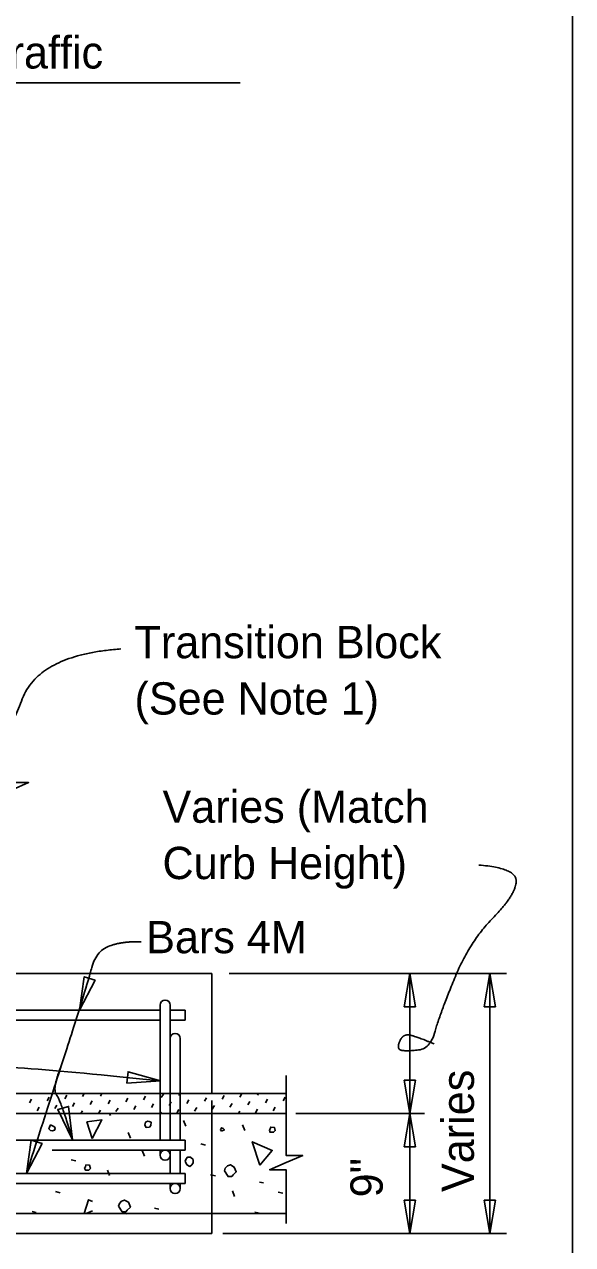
# Model space of a CAD drawing. Extents: x 0 to 41.1, y 0 to 25.9.
# Drawn here: x 37.62 to 41.05, y 6.17 to 13.8 of the extents above; entities that cross this region are included whole.
import ezdxf

# ---------------------------------------------------------------- set-up
doc = ezdxf.new("R2010")
doc.units = 0
for name, color, linetype in [('Dimension', 7, 'Continuous'), ('ExistSuperStruct', 7, 'Continuous'), ('Miscellaneous', 7, 'Continuous'), ('Miscellaneous1', 7, 'Continuous'), ('Rebar', 7, 'Continuous'), ('SubStrConc', 7, 'Continuous'), ('SubStrConc_h', 7, 'Continuous'), ('TextStructures', 7, 'Continuous')]:
    doc.layers.add(name, color=color, linetype=linetype)

msp = doc.modelspace()

# ---------------------------------------------------------------- linework, layer by layer
at = {"layer": 'Dimension'}
for p, q in [((38.8471, 13.433), (35.0367, 13.433)), ((35.76, 13.433), (38.9734, 13.433)), ((38.9734, 13.433), (38.8471, 13.433)), ((38.9044, 7.8689), (40.6367, 7.8689)), ((40.033, 7.8689), (40.033, 6.2439)), ((40.533, 7.8689), (40.533, 6.2439)), ((39.32, 6.9939), (40.1255, 6.9939)), ((38.8645, 6.2439), (40.6367, 6.2439))]:
    msp.add_line(p, q, dxfattribs=at)
for points in [[(0, 0), (41.0506, 0), (41.0506, 25.9461), (0, 25.9461)], [(40.033, 7.8689), (39.9978, 7.6607), (40.0683, 7.6607)], [(40.533, 7.8689), (40.4978, 7.6607), (40.5683, 7.6607)], [(37.9674, 7.6398), (38.0655, 7.8268), (37.9984, 7.8487)], [(38.4751, 7.1983), (38.2715, 7.2544), (38.2644, 7.1842)], [(40.033, 6.9939), (39.9978, 7.2022), (40.0683, 7.2022)], [(37.9247, 6.8286), (37.8998, 7.0383), (37.8321, 7.0184)], [(40.033, 6.9939), (39.9978, 6.7857), (40.0683, 6.7857)], [(37.6361, 6.6189), (37.7342, 6.806), (37.6671, 6.8278)], [(40.033, 6.2439), (40.0683, 6.4522), (39.9978, 6.4522)], [(40.533, 6.2439), (40.5683, 6.4522), (40.4978, 6.4522)]]:
    msp.add_lwpolyline(points, close=True, dxfattribs=at)
for points in [[(37.5468, 8.0879), (37.5468, 8.9711), (37.4435, 8.9711), (37.5468, 9.0161), (37.6502, 9.0611), (37.5468, 9.0611), (37.5468, 9.9341)], [(39.26, 6.3062), (39.26, 6.6422), (39.1566, 6.6422), (39.26, 6.6872), (39.3633, 6.7322), (39.26, 6.7322), (39.26, 7.2321)]]:
    msp.add_lwpolyline(points, dxfattribs=at)
for points, degree in [([(38.2272, 9.8963), (37.7131, 9.8611), (37.5023, 9.2938), (37.0685, 8.9512), (36.9144, 8.3516), (36.7889, 7.8777)], 2), ([(40.4643, 8.5462), (40.6974, 8.5286), (40.6983, 8.3646), (40.4072, 8.0677), (40.2189, 7.6109), (40.1618, 7.3997), (40.0134, 7.3825), (39.9506, 7.3939), (39.9849, 7.4853), (40.0534, 7.4853), (40.1846, 7.4282)], 2), ([(38.3527, 8.0668), (38.2292, 8.0701), (38.0689, 8.0067), (38.0155, 7.7829), (37.6361, 6.6189)], 2), ([(38.4751, 7.1982), (37.7447, 7.2724), (37.1209, 7.3194), (35.9507, 7.3277), (35.5209, 7.3197)], 3), ([(37.8541, 7.2906), (37.7956, 7.1501), (37.8533, 7.0712), (37.9247, 6.8286)], 2)]:
    msp.add_open_spline(points, degree=degree, dxfattribs=at)
at = {"layer": 'ExistSuperStruct'}
for p, q in [((39.26, 7.1191), (27.6853, 7.1191)), ((27.6853, 6.994), (39.26, 6.994)), ((39.26, 6.369), (32.9053, 6.369))]:
    msp.add_line(p, q, dxfattribs=at)
at = {"layer": 'Miscellaneous'}
for p, q in [((37.7653, 7.0734), (37.7783, 7.0958)), ((37.8759, 7.0864), (37.8889, 7.1088)), ((37.9866, 7.0993), (37.998, 7.1191)), ((38.0987, 7.1032), (38.1079, 7.1191)), ((38.2093, 7.1162), (38.211, 7.1191)), ((38.3688, 7.0803), (38.3818, 7.1027)), ((38.4794, 7.0933), (38.4924, 7.1157)), ((38.5901, 7.1063), (38.5975, 7.1191)), ((38.7495, 7.0704), (38.7625, 7.0928)), ((38.8602, 7.0834), (38.8731, 7.1058)), ((38.9708, 7.0963), (38.9838, 7.1187)), ((39.0814, 7.1093), (39.0871, 7.1191)), ((39.2409, 7.0734), (39.2539, 7.0958)), ((37.6547, 7.0605), (37.6676, 7.0828)), ((37.7035, 7.0116), (37.7165, 7.034)), ((37.8142, 7.0246), (37.8271, 7.047)), ((37.9248, 7.0375), (37.9377, 7.0599)), ((38.0354, 7.0505), (38.0484, 7.0729)), ((38.0865, 6.994), (38.0987, 7.015)), ((38.1475, 7.0544), (38.1605, 7.0768)), ((38.1964, 7.0056), (38.2093, 7.028)), ((38.2582, 7.0674), (38.2711, 7.0898)), ((38.307, 7.0185), (38.32, 7.0409)), ((38.4176, 7.0315), (38.4306, 7.0539)), ((38.5283, 7.0445), (38.5412, 7.0669)), ((38.5771, 6.9956), (38.5901, 7.018)), ((38.6389, 7.0574), (38.6519, 7.0798)), ((38.6877, 7.0086), (38.7007, 7.031)), ((38.7984, 7.0216), (38.8113, 7.044)), ((38.909, 7.0345), (38.922, 7.0569)), ((39.0196, 7.0475), (39.0326, 7.0699)), ((39.0685, 6.9987), (39.0814, 7.021)), ((39.1303, 7.0605), (39.1432, 7.0828)), ((39.1791, 7.0116), (39.1921, 7.034)), ((37.8736, 6.994), (37.8759, 6.9981)), ((37.9767, 6.994), (37.9866, 7.0111)), ((38.473, 6.994), (38.4794, 7.0051)), ((38.6325, 6.9146), (38.6183, 6.95)), ((38.8595, 6.994), (38.8602, 6.9951)), ((38.9626, 6.994), (38.9708, 7.0081)), ((38.2866, 6.8397), (38.2725, 6.8751)), ((39.0012, 6.8872), (38.9871, 6.9225)), ((38.7277, 6.8036), (38.756, 6.7965)), ((38.3744, 6.7272), (38.3602, 6.7626)), ((37.9165, 6.7044), (37.9448, 6.6973)), ((38.1558, 6.6064), (38.1434, 6.64)), ((38.788, 6.6106), (38.8181, 6.6053)), ((39.0941, 6.5647), (39.1189, 6.5611)), ((37.8184, 6.5061), (37.8467, 6.499)), ((38.9365, 6.4762), (38.9241, 6.5098)), ((39.2105, 6.5027), (39.2388, 6.4956)), ((37.6717, 6.3806), (37.6982, 6.3753)), ((38.438, 6.402), (38.4645, 6.3967)), ((39.0638, 6.3772), (39.0903, 6.3719))]:
    msp.add_line(p, q, dxfattribs=at)
for points in [[(38.0478, 6.8368), (38.0143, 6.9411), (38.1079, 6.9535), (38.0478, 6.8368)], [(38.16, 6.994), (38.158, 6.988), (38.1615, 6.981)], [(38.3769, 6.9216), (38.3857, 6.9057), (38.4052, 6.9075), (38.414, 6.9198), (38.4158, 6.9393), (38.4034, 6.9446), (38.3946, 6.9464), (38.384, 6.9428), (38.3804, 6.9393), (38.3769, 6.9216)], [(37.788, 6.8871), (37.8004, 6.8853), (37.8127, 6.8906), (37.8163, 6.9012), (37.811, 6.91), (37.8004, 6.9171), (37.788, 6.9224), (37.7809, 6.9083), (37.7774, 6.8977), (37.788, 6.8871)], [(38.8549, 6.884), (38.8743, 6.8928), (38.8673, 6.8999), (38.8549, 6.9052), (38.8496, 6.8928), (38.8549, 6.884)], [(39.1604, 6.8769), (39.1816, 6.8769), (39.1922, 6.8875), (39.1869, 6.9069), (39.1639, 6.9087), (39.1604, 6.8981), (39.1551, 6.8892), (39.1604, 6.8769), (39.1569, 6.8804)], [(39.0953, 6.6711), (39.0476, 6.8178), (39.1731, 6.763), (39.0953, 6.6711)], [(38.6289, 6.6954), (38.6395, 6.6742), (38.6572, 6.6636), (38.6713, 6.6742), (38.6784, 6.6848), (38.6784, 6.706), (38.6625, 6.7219), (38.6431, 6.7202), (38.6342, 6.7113), (38.6289, 6.6954)], [(38.0051, 6.6405), (38.0263, 6.6405), (38.0369, 6.6511), (38.0316, 6.6706), (38.0086, 6.6723), (38.0051, 6.6617), (37.9998, 6.6529), (38.0051, 6.6405), (38.0015, 6.6441)], [(38.8742, 6.6365), (38.8972, 6.5994), (38.9202, 6.6012), (38.929, 6.61), (38.9485, 6.6294), (38.9361, 6.6595), (38.9114, 6.6736), (38.8937, 6.6666), (38.8796, 6.6524), (38.8742, 6.6365)], [(37.9976, 6.369), (38.024, 6.4548), (38.0487, 6.445)], [(38.2124, 6.4159), (38.2354, 6.3787), (38.2583, 6.3805), (38.2672, 6.3894), (38.2866, 6.4088), (38.2743, 6.4389), (38.2495, 6.453), (38.2318, 6.4459), (38.2177, 6.4318), (38.2124, 6.4159)], [(38.0487, 6.3867), (38.0094, 6.369)], [(38.2632, 6.3656), (38.2612, 6.3666), (38.2596, 6.3656)]]:
    msp.add_lwpolyline(points, dxfattribs=at)
at = {"layer": 'Miscellaneous1'}
msp.add_lwpolyline([(0, 25.9461), (41.0506, 25.9461), (41.0506, 0), (0, 0)], close=True, dxfattribs=at)
at = {"layer": 'Rebar'}
for p, q in [((37.2954, 7.6398), (38.4725, 7.6398)), ((38.4725, 7.671), (38.4725, 6.8272)), ((38.535, 6.8272), (38.535, 7.671)), ((38.535, 7.6398), (38.6287, 7.6398)), ((38.6287, 7.5773), (38.6287, 7.6398)), ((37.2954, 7.5773), (38.4725, 7.5773)), ((38.535, 7.5773), (38.6287, 7.5773)), ((38.5975, 6.8272), (38.5975, 7.4627)), ((35.9621, 6.8272), (38.6287, 6.8272)), ((38.6287, 6.8272), (38.6287, 6.7647)), ((37.7975, 6.7647), (38.6287, 6.7647)), ((38.4725, 6.7647), (38.4725, 6.7335)), ((38.535, 6.6189), (38.535, 6.7647)), ((38.5975, 6.6189), (38.5975, 6.7647)), ((35.9621, 6.6189), (38.6287, 6.6189)), ((38.6287, 6.6189), (38.6287, 6.5564)), ((35.9621, 6.5564), (38.6287, 6.5564)), ((38.535, 6.5252), (38.535, 6.5564)), ((38.5975, 6.5252), (38.5975, 6.5564))]:
    msp.add_line(p, q, dxfattribs=at)
for centre in [(38.5037, 6.7335), (38.5662, 6.5252)]:
    msp.add_circle(centre, 0.0312, dxfattribs=at)
for centre in [(38.5037, 7.671), (38.5662, 7.4627)]:
    msp.add_arc(centre, 0.0312, 0, 180, dxfattribs=at)
at = {"layer": 'SubStrConc'}
for p, q in [((35.7954, 7.8689), (38.7954, 7.8689)), ((38.7954, 7.8689), (38.7954, 7.119))]:
    msp.add_line(p, q, dxfattribs=at)
at = {"layer": 'SubStrConc_h'}
for p, q in [((35.7954, 7.119), (38.7954, 7.119)), ((38.7954, 7.076), (38.7954, 6.2439)), ((35.7954, 6.2439), (38.7954, 6.2439))]:
    msp.add_line(p, q, dxfattribs=at)

# ---------------------------------------------------------------- texts
at = {"layer": 'Dimension'}
for s, p in [('Transition Block', (38.3122, 9.8386)), ('(See Note 1)', (38.3122, 9.4866)), ('Varies (Match', (38.4871, 8.8105)), ('Curb Height)', (38.4871, 8.4585))]:
    msp.add_text(s, height=0.2016, dxfattribs=at).set_placement(p)
at = {"layer": 'TextStructures'}
for s, rotation, p in [('Direction of Traffic', 359.99977, (35.9286, 13.5233)), ('Varies', 90, (40.4337, 6.5032)), ('9"', 90, (39.8634, 6.4699))]:
    msp.add_text(s, height=0.2016, rotation=rotation, dxfattribs=at).set_placement(p)
msp.add_text('Bars 4M', height=0.2016, dxfattribs=at).set_placement((38.385, 7.9954))

doc.saveas('drawing.dxf')
